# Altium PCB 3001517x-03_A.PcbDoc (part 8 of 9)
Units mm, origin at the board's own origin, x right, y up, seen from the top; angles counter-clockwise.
Board outline 100 x 72 mm, 10 copper layers (Top, GND_2, Signal_3, Signal_4, PWR_5, GND_6, Signal_7, Signal_8, GND_9, Bottom), stack 1.6 mm thick; 602 components, 497 nets, 2372 pads, 1602 vias.
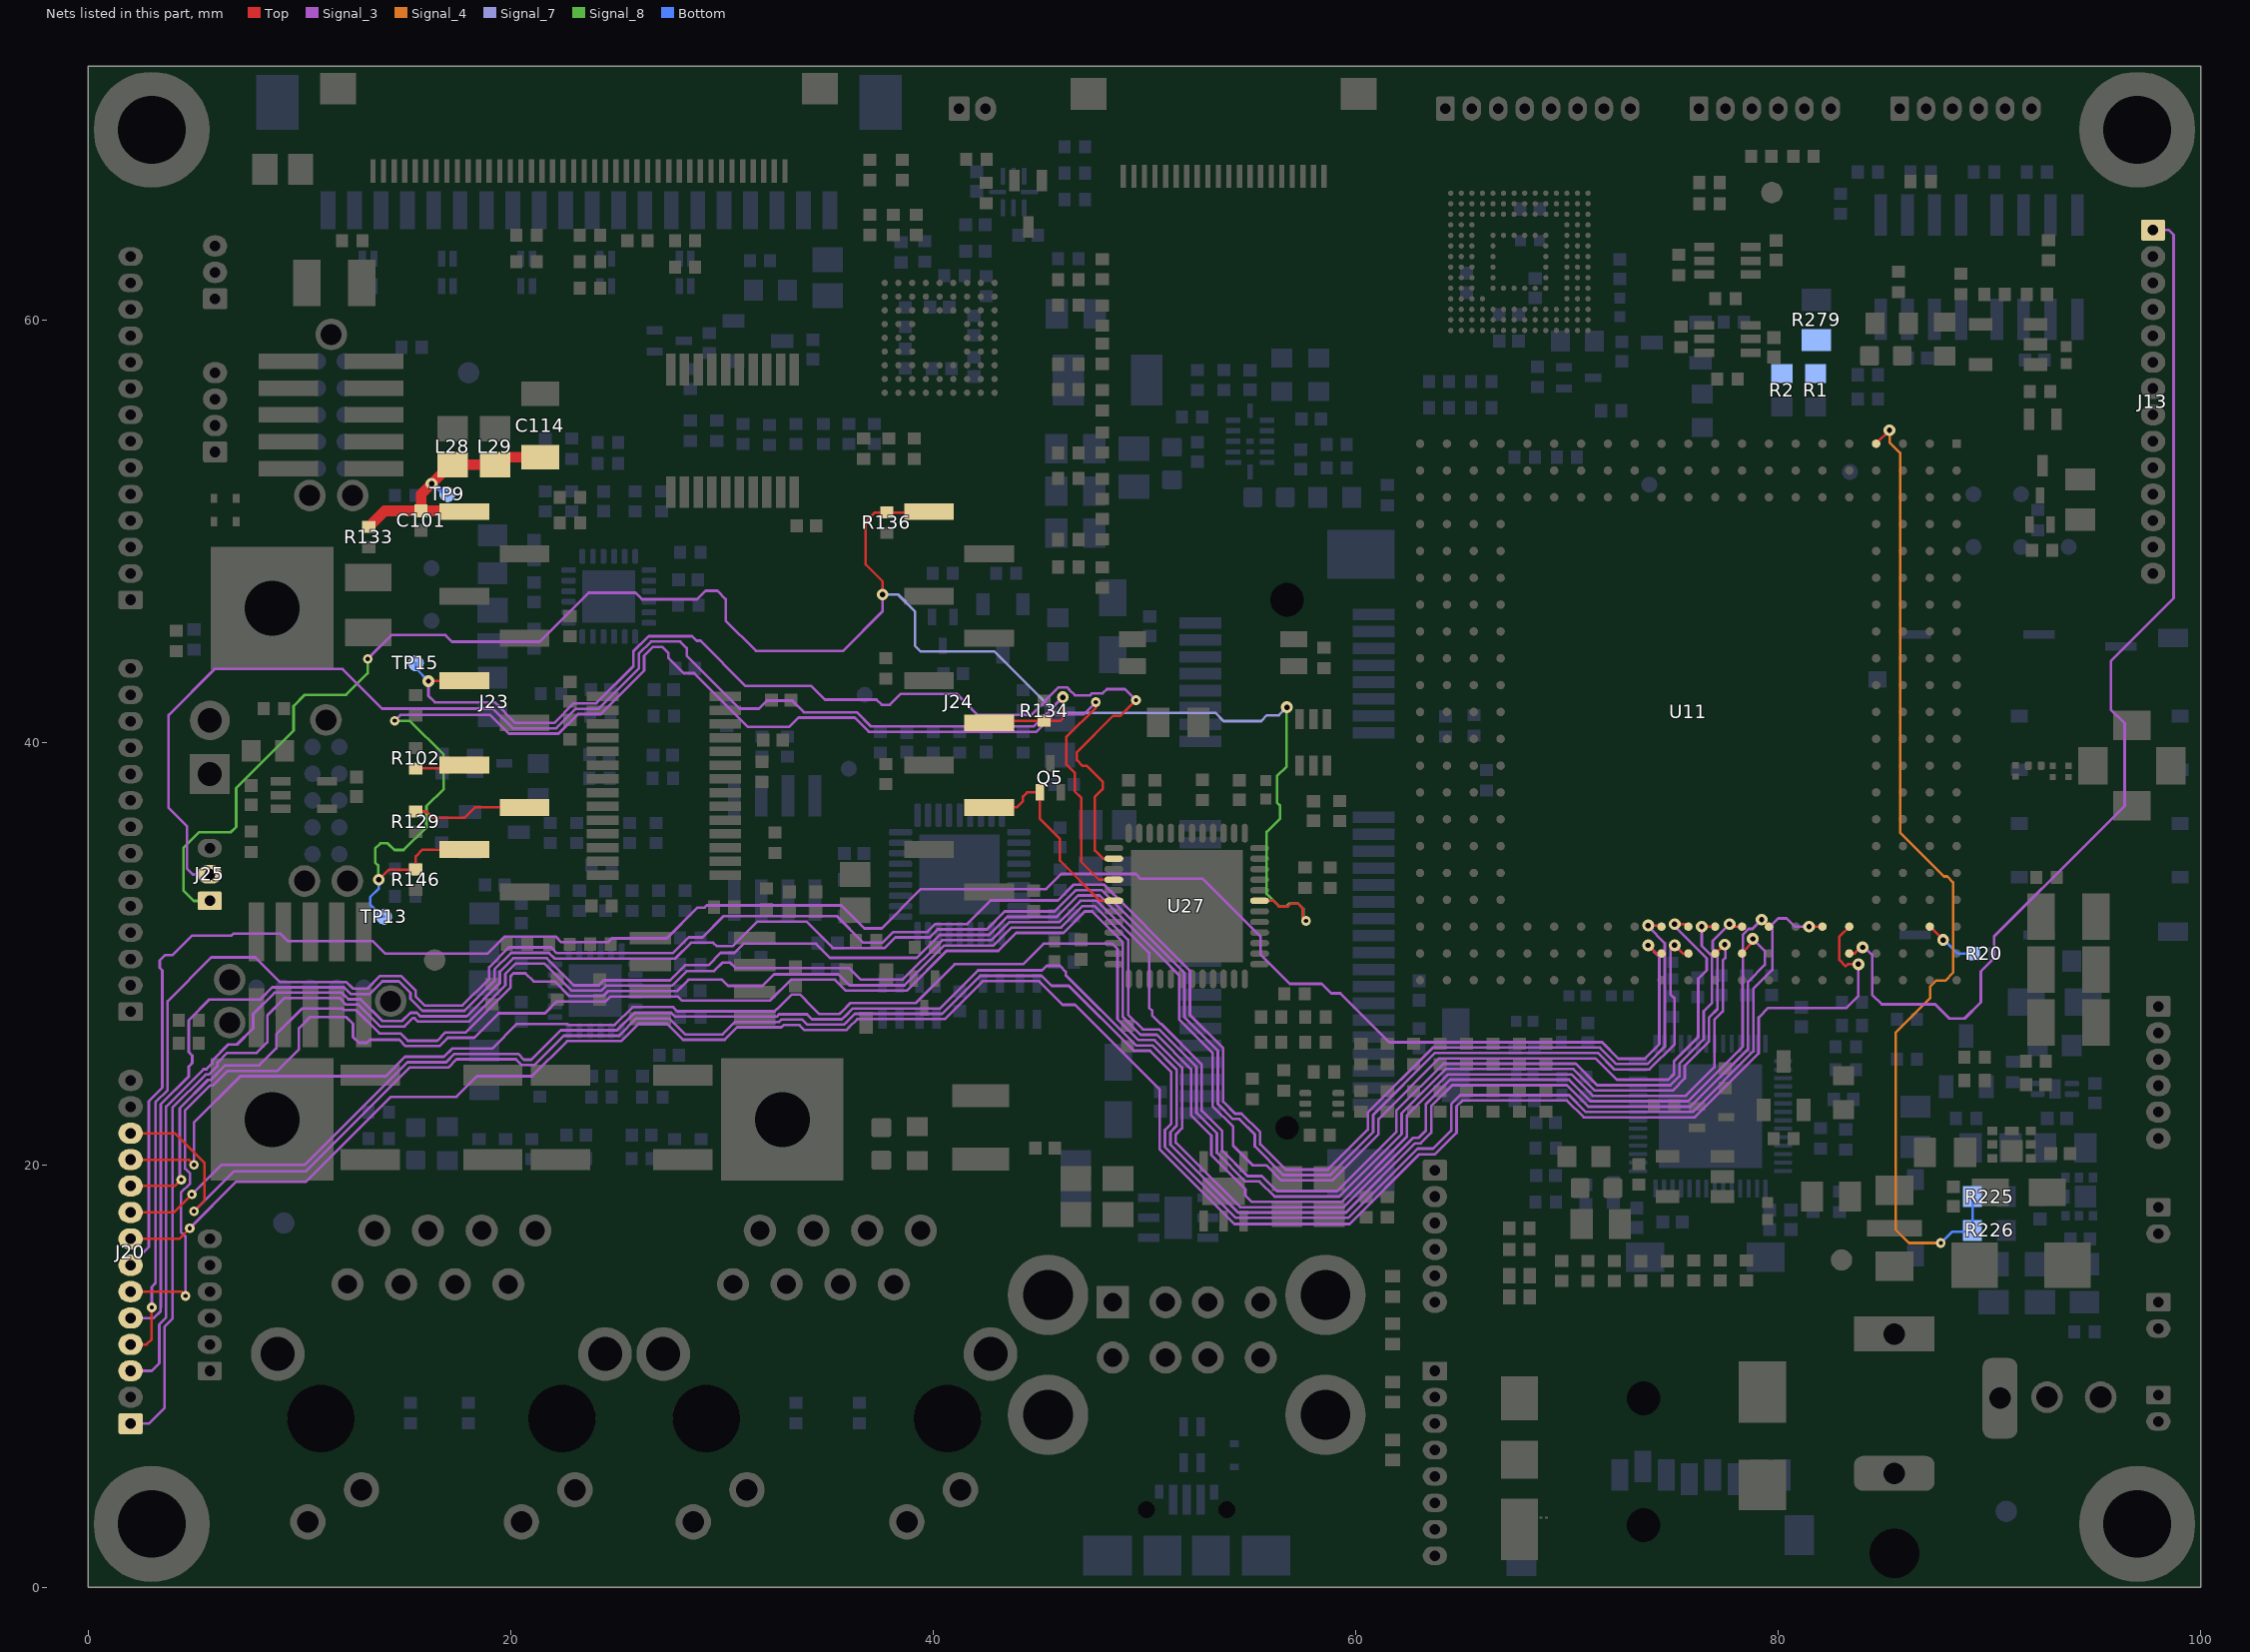
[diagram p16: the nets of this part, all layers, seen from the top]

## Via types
v1: diameter 0.56, hole 0.25, Top to Bottom, tented both sides, 1002 vias
v2: diameter 0.46, hole 0.2, Top to Bottom, tented both sides, 468 vias
v3: diameter 0.457, hole 0.2, Top to Bottom, tented both sides, 132 vias

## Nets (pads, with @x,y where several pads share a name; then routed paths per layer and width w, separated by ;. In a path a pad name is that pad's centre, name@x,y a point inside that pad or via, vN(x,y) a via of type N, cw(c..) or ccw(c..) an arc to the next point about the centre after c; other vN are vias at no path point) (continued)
VPWR: R225.2 R226.2 U11.D1 | length 47.2
  Top w0.125: U11.D1@84.64,54.14 v1(85.275,54.775)
  Signal_4 w0.125: v1(85.275,54.775) 85.275,54.2 85.776,53.699 85.776,35.724 87.845,33.655 88.009,33.655 88.285,33.379 88.285,32.991 88.284,32.109 88.285,31.721 88.284,30.839 88.285,30.451 88.284,29.1 87.909,28.725 87.475,28.725 87.2,28.45 87.2,27.9 85.572,26.272 85.572,16.928 86.2,16.3 v2(87.7,16.3)
  Bottom w0.125: v2(87.7,16.3) 88.23,16.83 89.2,16.83 R226.2@89.2,16.9 R225.2@89.2,18.5
VSYS: R1.1 R2.1 R279.2
WL_EN: J13.1 U11.E20 | length 51.1
  Top w0.119: U11.E20@83.37,30.01 83.624,30.01 84,30.386 v1(84,30.3)
  Signal_3 w0.127: v1(84,30.3) 84,30.395 84.45,29.945 84.45,28.058 84.908,27.6 87.434,27.6 88.105,26.929 88.829,26.929 89.6,27.7 89.6,29.165 90.221,29.786 90.221,30.805 94.788,35.372 96.408,36.992 96.408,40.902 95.753,41.557 95.753,43.853 98.724,46.824 98.724,64.026 98.5,64.25 98.15,64.25 J13.1@97.75,64.25
WLAN_LED: R20.2 U11.B19 | length 2.6
  Top w0.125: U11.B19@87.18,31.28 v1(87.815,30.645)
  Bottom w0.125: v1(87.815,30.645) 87.855,30.645 88.5,30 R20.2@89.27,30
WLAN_SD1_CLK: J20.1 U11.K19 | length 117.2
  Top w0.119: v1(76.385,31.28) U11.K19@77.02,31.28
  Signal_3 w0.127: J20.1@2,7.75 2.858,7.75 3.608,8.5 3.608,12.347 3.981,12.72 3.981,22.699 5.557,24.276 5.691,24.276 6.115,24.7 6.115,24.834 6.582,25.3 7.965,25.3 8.47,25.805 8.47,27.07 9.3,27.9 11.893,27.9 12.208,27.585 12.787,27.585 13.816,26.556 14.962,26.556 15.351,26.946 15.444,26.946 15.605,26.785 18.02,26.785 19.738,28.503 19.738,29.044 20.227,29.532 21.595,29.532 22.881,28.246 24.274,28.246 24.51,28.482 27.642,28.482 28.339,29.179 29.631,29.179 30.029,29.577 30.377,29.577 30.634,29.321 36.014,29.321 36.555,28.78 38.557,28.78 40.416,30.638 42.751,30.638 43.601,31.488 45.95,31.488 46.965,32.503 47.762,32.503 50.22,30.045 50.22,27.445 50.37,27.295 50.37,27.064 50.764,26.67 50.791,26.67 52.714,24.748 52.714,22.57 53.678,21.605 53.678,20.677 54.881,19.475 55.55,19.475 56.265,18.759 59.119,18.759 61.92,21.561 61.92,22.557 64.154,24.791 70.414,24.791 71.43,23.775 74.9,23.775 75.324,24.2 75.324,24.8 76.473,25.948 76.473,27.084 76.473,27.281 76.873,27.681 76.873,29.881 76.385,30.369 v1(76.385,31.28)
WLAN_SD1_CMD: J20.3 U11.L19 | length 114.2
  Top w0.119: v1(75.1,31.4) 75.63,31.4 U11.L19@75.75,31.28
  Signal_3 w0.127: J20.3@2,10.25 3,10.25 3.354,10.604 3.354,12.452 3.683,12.781 3.683,22.761 5.452,24.53 5.586,24.53 5.861,24.805 5.861,24.939 6.622,25.7 7.035,25.7 7.8,26.465 7.8,27.141 8.813,28.154 11.998,28.154 12.313,27.839 12.892,27.839 13.921,26.81 14.856,26.81 15.246,27.2 15.549,27.2 15.71,27.039 17.915,27.039 19.484,28.608 19.484,29.149 20.121,29.786 21.7,29.786 22.986,28.5 24.168,28.5 24.405,28.736 27.536,28.736 28.254,29.454 29.354,29.454 29.939,30.039 30.589,30.039 31.02,30.471 34.446,30.471 35.116,29.8 39.218,29.8 40.31,30.892 42.646,30.892 43.496,31.742 45.845,31.742 46.86,32.757 47.867,32.757 48.883,31.742 50.833,29.792 51.639,28.986 51.639,26.885 53.222,25.302 53.222,22.781 54.2,21.802 54.2,20.9 55.117,19.983 55.761,19.983 56.476,19.267 58.894,19.267 61.079,21.453 61.079,22.174 63.95,25.045 71.35,25.045 72.365,24.029 74.795,24.029 75.07,24.305 75.07,24.905 76.219,26.054 76.219,28.819 76.619,29.219 76.619,29.776 75.1,31.295 v1(75.1,31.4)
WLAN_SD1_D4/GPIO4: J20.8 U11.E19 | length 105.3
  Top w0.119: J20.8@2,16.5 4.3,16.5 v3(4.8,17) ; U11.E19@83.37,31.28 82.9,30.81 82.9,29.7 83.2,29.4 83.3,29.5 v1(83.8,29.5)
  Signal_3 w0.127: v3(4.8,17) 7,19.2 10.3,19.2 14.32,23.22 17.42,23.22 18.4,24.2 21.001,24.2 22.664,25.863 25.236,25.863 26.05,26.677 27.399,26.677 28.151,25.925 30.125,25.925 30.712,26.512 32.808,26.512 32.916,26.62 33.674,26.62 33.911,26.384 35.884,26.384 36.013,26.513 36.016,26.513 36.402,26.9 40.534,26.9 42.332,28.698 45.007,28.698 46.126,27.579 46.713,27.579 50.718,23.575 50.718,20.739 54.257,17.2 59.714,17.2 63.014,20.5 63.754,20.5 64.774,21.521 64.774,22.774 65.05,23.05 70,23.05 70.799,22.251 76.054,22.251 79.079,25.277 79.079,26.974 79.091,26.986 79.091,26.991 79.53,27.43 83.23,27.43 83.8,28 v1(83.8,29.5)
WLAN_SD1_D5/GPIO3: J20.9 U11.J20 | length 100.9
  Top w0.119: J20.9@2,17.75 4.05,17.75 v3(4.9,18.6) ; U11.J20@78.29,30.01 78.29,30.04 78.8,30.55 v1(78.8,30.7)
  Signal_3 w0.127: v3(4.9,18.6) 6.3,20 10.241,20 15.104,24.864 16.939,24.864 17.329,25.254 20.351,25.254 20.626,24.98 20.974,24.98 22.366,26.371 25.025,26.371 25.854,27.2 27.595,27.2 27.775,27.02 32.598,27.02 32.706,27.128 34.025,27.128 34.262,26.892 35.674,26.892 35.803,27.021 35.805,27.021 36.192,27.408 40.323,27.408 42.121,29.206 45.151,29.206 45.366,29.42 45.995,29.42 46.27,29.145 46.27,28.986 49.603,25.654 50.37,25.654 51.524,24.5 51.524,21.849 51.226,21.55 51.226,20.95 54.432,17.743 59.54,17.743 62.822,21.026 63.079,21.026 63.574,21.521 63.574,22.774 64.575,23.775 69.993,23.775 71.009,22.759 75.843,22.759 78.571,25.488 78.571,28.671 79.37,29.47 79.37,30.129 v1(78.8,30.7)
WLAN_SD1_D6/GPIO2: J20.10 U11.J19 | length 107
  Top w0.119: J20.10@2,19 4.1,19 v3(4.4,19.3) ; v1(77.7,31.4) 77.82,31.28 U11.J19@78.29,31.28
  Signal_3 w0.127: v3(4.4,19.3) 4.327,19.373 4.327,22.686 5.662,24.022 5.796,24.022 6.483,24.708 8.09,24.708 8.9,25.518 8.9,26.192 10.108,27.4 12.034,27.4 12.103,27.331 12.669,27.331 13.773,26.227 14.778,26.227 15.126,25.88 16.518,25.88 16.909,26.27 17.865,26.27 19.992,28.398 19.992,28.939 20.124,29.071 20.695,29.071 21.086,28.679 22.088,28.679 22.776,27.992 24.379,27.992 24.615,28.228 27.865,28.228 28.407,28.77 29.995,28.77 30.286,28.479 31.92,28.479 32.465,29.024 35.5,29.024 36.025,28.5 38.637,28.5 40.521,30.384 42.856,30.384 43.706,31.234 46.055,31.234 47.071,32.249 47.629,32.249 49.23,30.649 49.23,27.105 49.919,26.416 50.686,26.416 52.46,24.643 52.46,22.465 53.424,21.5 53.424,20.572 54.776,19.221 55.445,19.221 56.16,18.505 59.224,18.505 62.174,21.456 62.174,22.452 64.259,24.537 70.309,24.537 71.325,23.521 75.005,23.521 75.578,24.095 75.578,24.695 76.727,25.843 76.727,26.979 77.127,27.379 77.127,29.986 76.9,30.213 76.9,30.6 v1(77.7,31.4)
WLAN_SD1_D7/GPIO1: J20.11 U11.H19 | length 104.2
  Top w0.119: J20.11@2,20.25 4.75,20.25 v3(5,20) ; v1(79.221,31.61) 79.23,31.61 U11.H19@79.56,31.28
  Signal_3 w0.127: v3(5,20) 5,22 7.2,24.2 14.082,24.2 14.999,25.118 16.834,25.118 17.224,25.508 19.117,25.508 20.28,26.671 22.676,26.671 22.721,26.625 24.92,26.625 25.761,27.466 27.688,27.466 27.88,27.274 32.493,27.274 32.601,27.382 32.617,27.382 33.126,27.891 33.305,28.071 33.695,28.071 33.97,27.795 33.97,27.77 34.595,27.146 35.568,27.146 35.698,27.275 35.7,27.275 36.087,27.662 39.17,27.662 41.008,29.5 44.256,29.5 45.227,30.471 48.479,30.471 48.722,30.228 48.722,26.895 49.708,25.908 50.476,25.908 51.778,24.605 51.778,21.744 51.48,21.445 51.48,21.055 54.537,17.997 59.434,17.997 62.716,21.28 62.974,21.28 63.32,21.626 63.32,22.88 64.47,24.029 70.099,24.029 71.114,23.013 75.738,23.013 78.317,25.593 78.317,28.777 78.329,28.789 78.329,30.895 78.605,31.17 78.781,31.17 v1(79.221,31.61)
WLAN_SD1_DATA0: J20.4 U11.M19 | length 113.6
  Top w0.119: J20.4@2,11.5 2.75,11.5 3,11.75 v3(3,13.25) ; v1(73.845,31.332) 74.428,31.332 U11.M19@74.48,31.28
  Signal_3 w0.127: v3(3,13.25) 3,14.225 3.175,14.4 3.175,22.971 3.75,23.546 3.75,27.75 5.82,29.82 7.906,29.82 9.064,28.662 12.208,28.662 12.523,28.347 13.219,28.347 13.816,28.944 14.804,28.944 15.504,28.244 15.504,27.964 15.921,27.547 17.705,27.547 18.976,28.819 18.976,29.359 19.911,30.294 21.911,30.294 22.185,30.019 27.666,30.019 28.421,30.774 29.074,30.774 30.074,31.774 35.445,31.774 36.7,30.52 37.595,30.52 38.1,31.024 39.725,31.024 40.1,31.4 41.604,31.4 42.124,31.92 42.125,31.92 42.726,32.52 45.905,32.52 46.65,33.265 48.078,33.265 49.093,32.25 51.043,30.3 ; 51.043,30.3 52.147,29.196 52.147,27.095 53.73,25.513 53.73,22.991 54.291,22.43 54.595,22.43 55.474,21.55 55.474,20.987 56.686,19.775 58.683,19.775 60.571,21.664 60.571,22.471 63.653,25.553 71.56,25.553 72.338,24.775 73.8,24.775 74.63,25.605 74.63,30.496 73.845,31.28 v1(73.845,31.332)
WLAN_SD1_DATA1: J20.5 U11.L20 | length 110.2
  Top w0.119: v1(75.1,30.4) 75.49,30.01 U11.L20@75.75,30.01
  Signal_3 w0.127: J20.5@2,12.75 3.093,12.75 3.419,13.076 3.419,13.24 3.429,13.25 3.429,22.866 4.75,24.187 4.75,24.655 4.92,24.826 4.92,25.174 4.75,25.345 4.75,26.85 5.726,27.826 8.126,27.826 8.708,28.408 12.103,28.408 12.418,28.093 13.324,28.093 13.921,28.69 14.699,28.69 15.25,28.139 15.25,27.859 15.816,27.293 17.81,27.293 19.23,28.713 19.23,29.254 20.016,30.04 21.805,30.04 22.08,29.765 27.771,29.765 28.526,30.52 29.585,30.52 29.755,30.35 30.5,30.35 31.67,31.52 33.995,31.52 35.25,30.266 37.7,30.266 38.205,30.77 39.83,30.77 40.205,31.146 42.541,31.146 43.391,31.996 45.739,31.996 46.755,33.011 47.972,33.011 48.988,31.996 50.938,30.046 51.893,29.091 51.893,26.99 53.476,25.407 53.476,22.886 54.186,22.176 54.49,22.176 55.22,21.445 55.22,20.882 56.581,19.521 58.789,19.521 60.825,21.558 60.825,22.366 63.758,25.299 71.455,25.299 72.232,24.521 73.905,24.521 75.1,25.716 75.1,27.876 74.9,28.076 74.9,30.2 v1(75.1,30.4)
WLAN_SD1_DATA2: J20.6 U11.K20 | length 111.4
  Top w0.119: J20.6@2,14 4.4,14 v3(4.6,13.8) ; U11.K20@77.02,30.01 77.051,30.01 v1(77.47,30.429)
  Signal_3 w0.127: v3(4.6,13.8) 4.6,16.607 4.381,16.826 4.381,18.688 4.819,19.126 4.819,19.588 4.581,19.826 4.581,22.581 5.767,23.768 5.902,23.768 6.588,24.454 8.954,24.454 9.969,25.469 9.969,26.469 10.5,27 12.2,27 12.529,26.671 12.529,26.055 12.805,25.78 13.195,25.78 13.34,25.925 14.721,25.925 15.021,25.626 16.623,25.626 17.014,26.016 18.266,26.016 19.429,27.179 21.619,27.179 22.179,27.738 24.484,27.738 24.721,27.974 27.898,27.974 28.09,27.782 32.282,27.782 33.27,28.77 35.346,28.77 35.87,28.246 38.742,28.246 40.626,30.13 43.08,30.13 43.93,30.98 46.16,30.98 47.176,31.995 47.524,31.995 48.976,30.544 48.976,27 49.813,26.162 50.581,26.162 52.206,24.537 52.206,22.36 53.17,21.395 53.17,20.466 54.78,18.857 54.78,18.555 55.083,18.251 59.329,18.251 62.428,21.351 62.428,22.347 64.365,24.283 70.204,24.283 71.219,23.267 75.633,23.267 76.981,24.616 76.981,26.874 77.381,27.274 77.381,29.681 77.5,29.8 77.5,30.399 v1(77.47,30.429)
WLAN_SD1_DATA3: J20.7 U11.M20 | length 99.8
  Top w0.119: v1(73.845,30.391) 74.226,30.01 U11.M20@74.48,30.01
  Signal_3 w0.127: J20.7@2,15.25 2.86,16.11 2.86,23.015 3.496,23.651 3.496,29.209 3.38,29.326 3.38,29.679 3.625,29.925 3.979,29.925 4.91,30.856 6.773,30.856 6.87,30.953 9.088,30.953 9.441,30.6 13.459,30.6 14.063,29.996 18.896,29.996 19.7,30.8 22.141,30.8 22.246,30.695 22.246,30.674 22.372,30.548 23.171,30.548 23.173,30.546 24.605,30.546 24.785,30.725 27.388,30.725 28.842,32.179 29.174,32.179 29.275,32.28 35.655,32.28 36.738,31.197 37.557,31.197 39.413,33.053 45.344,33.053 46.062,33.771 49.588,33.771 49.817,33.542 52.758,33.542 55.5,30.8 55.5,29.95 56.427,29.023 56.427,29.021 56.878,28.57 58.395,28.57 58.845,28.12 59.274,28.12 61.588,25.807 71.665,25.807 72.443,25.029 73.695,25.029 74.376,25.71 74.376,29.861 v1(73.845,30.391)
WLAN_SDIO_INT_L: J20.12 U11.F19 | length 107
  Top w0.119: J20.12@2,21.5 4.087,21.5 5.5,20.087 5.5,18.3 v3(5,17.8) ; v1(81.465,31.28) U11.F19@82.1,31.28
  Signal_3 w0.127: v3(5,17.8) 6.9,19.7 10.3,19.7 15.209,24.61 17.044,24.61 17.435,25 20.246,25 20.521,24.726 21.118,24.726 22.51,26.117 25.131,26.117 25.944,26.931 27.504,26.931 28.256,26.179 30.02,26.179 30.607,26.766 32.703,26.766 32.811,26.874 33.8,26.874 34.036,26.638 35.779,26.638 35.908,26.767 35.91,26.767 36.297,27.154 40.429,27.154 42.227,28.952 45.133,28.952 45.605,28.48 46.418,28.48 49.498,25.4 50.265,25.4 51.27,24.395 51.27,21.954 50.972,21.655 50.972,20.845 54.327,17.489 59.645,17.489 62.927,20.772 63.666,20.772 64.52,21.626 64.52,22.88 64.945,23.304 70.105,23.304 70.904,22.505 75.948,22.505 78.825,25.382 78.825,28.325 79.725,29.224 79.725,31.39 80.005,31.67 80.395,31.67 80.785,31.28 v1(81.465,31.28)
XBEE_ASSOC: J24.6 J25.2 R134.1 | length 62.7
  Top w0.119: J24.6@42.65,40.925 42.745,41.02 R134.1@45.25,41.02 46.02,41.02 46.135,41.135 v1(46.135,42.135)
  Signal_3 w0.127: J25.2@5.75,33.75 4.95,33.75 4.666,34.034 4.666,36.034 3.8,36.9 3.8,41.3 5.971,43.47 12.035,43.47 13.905,41.6 19.158,41.6 20.09,40.668 22.154,40.668 23.079,41.593 24.153,41.593 26.059,43.499 26.059,44.2 26.633,44.774 28.02,44.774 28.329,44.465 28.329,44.105 30.834,41.6 31.75,41.6 32.122,41.972 33.322,41.972 33.868,41.426 36.384,41.426 37.056,40.754 44.754,40.754 v1(46.135,42.135)
XBEE_IDENT/IO33: J24.1 J25.1 R136.1 U27.43 | length 92.5
  Top w0.119: v1(37.6,47) 37.6,47.616 36.8,48.416 36.8,50.45 37.23,50.88 R136.1@37.8,50.88 39.755,50.88 J24.1@39.8,50.925 ; U27.43@55.45,32.5 56.113,32.5 56.378,32.235 56.796,32.235 56.927,32.366 57.273,32.366 57.516,32.123 57.516,31.684 v3(57.65,31.55)
  Signal_3 w0.127: v3(13.226,43.95) 14.354,45.078 16.905,45.078 17.216,44.767 21.368,44.767 23.678,47.078 25.905,47.078 26.211,46.773 28.819,46.773 29.221,47.175 29.779,47.175 30.174,46.779 30.174,45.761 31.601,44.334 35.734,44.334 37.6,46.2 v1(37.6,47)
  Signal_8 w0.127: J25.1@5.75,32.5 5,32.5 4.5,33 4.5,35 5.25,35.75 6.75,35.75 7,36 7,37.835 9.72,40.555 9.72,41.72 10.25,42.25 12.201,42.25 13.226,43.274 v3(13.226,43.95) ; v1(56.743,41.661) 56.728,41.647 56.728,38.862 56.272,38.405 56.272,37.153 56.424,37 56.424,36.4 55.782,35.757 55.782,32.826 56.376,32.231 56.724,32.231 56.863,32.37 57.274,32.37 57.52,32.124 57.52,31.679 v3(57.65,31.55)
  Signal_7 w0.127: v1(37.6,47) 38.335,47 39.133,46.201 39.133,44.567 39.401,44.299 42.901,44.299 45.8,41.4 53.353,41.4 53.746,41.007 55.523,41.007 55.799,41.283 56.365,41.283 v1(56.743,41.661)
XBEE_ON/SLP_N/IO11: J24.8 Q5.G U27.18 | length 9.8
  Top w0.119: J24.8@42.65,36.925 43.956,36.925 44.25,37.219 44.25,37.446 44.439,37.635 Q5.G@45.05,37.635 45.05,36.375 46,35.425 46,34.4 47.9,32.5 U27.18@48.55,32.5
XBEE_RSTN/IO7: J23.5 TP15.1 U27.14 | length 53
  Top w0.119: v1(16.1,42.9) 17.775,42.9 J23.5@17.8,42.925 ; U27.14@48.55,34.5 48.04,34.5 47.658,34.882 47.658,37.429 48.015,37.786 48.015,38.144 47.28,38.88 47.075,38.88 46.802,39.153 46.802,39.539 48.524,41.261 48.861,41.261 v2(49.6,42)
  Signal_3 w0.127: v1(16.1,42.9) 16.1,42.2 16.4,41.9 19.242,41.9 20.22,40.922 22.049,40.922 22.974,41.847 24.048,41.847 25.805,43.604 25.805,44.306 26.528,45.028 28.584,45.028 28.801,44.812 28.974,44.812 31.115,42.671 34.223,42.671 34.874,42.02 37.314,42.02 37.555,41.779 37.945,41.779 38.465,42.3 41.1,42.3 42.1,41.3 44.635,41.3 45.941,42.606 46.331,42.606 46.429,42.508 46.429,42.505 46.705,42.229 47.435,42.229 47.526,42.32 48.02,42.32 48.22,42.52 49.08,42.52 v2(49.6,42)
  Bottom w0.119: TP15.1@15.5,43.75 15.5,43.5 v1(16.1,42.9)
XBEE_SLP_RQ/IO9: J23.9 R146.2 TP13.1 U27.16 | length 67.5
  Top w0.119: v1(13.75,33.5) 14.23,33.98 R146.2@15.5,33.98 15.5,34.6 15.825,34.925 J23.9@17.8,34.925 ; v2(47.7,41.9) 47.7,41.655 46.31,40.265 46.31,38.949 46.695,38.565 46.695,37.685 46.999,37.381 46.999,34.351 47.85,33.5 U27.16@48.55,33.5
  Signal_3 w0.127: v3(14.5,41.025) 14.775,41.3 19.022,41.3 19.908,40.414 22.259,40.414 23.184,41.339 24.258,41.339 26.313,43.394 26.313,44.095 26.738,44.52 27.174,44.52 27.464,44.231 27.464,44 27.489,43.974 27.489,43.969 28.185,43.272 28.685,43.272 31.228,40.729 33.178,40.729 33.621,41.172 36.278,41.172 36.951,40.5 44.889,40.5 45.731,41.342 47.142,41.342 v2(47.7,41.9)
  Signal_8 w0.127: v1(13.75,33.5) 13.72,33.529 13.72,34.174 13.579,34.315 13.579,34.974 13.826,35.22 14.174,35.22 14.49,34.905 14.927,34.905 16.003,35.981 16.003,36.981 16.822,37.801 16.822,39.412 15.209,41.025 v3(14.5,41.025)
  Bottom w0.119: v1(13.75,33.5) 13.75,33.087 13.335,32.672 13.335,32.328 13.444,32.219 13.913,31.75 TP13.1@14,31.75
XBEE_USB_N: J23.8 R129.2 | length 5.5
  Top w0.127: R129.2@15.5,36.73 16.008,36.73 16.309,36.429 17.804,36.429 18.301,36.925 J23.8@20.65,36.925
XBEE_USB_P: J23.7 R102.2 | length 2.4
  Top w0.127: R102.2@15.5,38.77 17.645,38.77 J23.7@17.8,38.925
XBEE_VCC: C101.2 C114.2 J23.1 L28.2 L29.2 R133.1 TP9.1 | length 13.1
  Top w0.5: R133.1@13.275,50.205 14.03,50.96 C101.2@15.75,50.96 ; J23.1@17.8,50.925 17.765,50.96 C101.2@15.75,50.96 ; C114.2@21.395,53.5 19.25,53.5 L29.2@19.25,53.15 L28.2@17.25,53.15 17.15,53.15 v1(16.25,52.25) 15.75,51.75 C101.2@15.75,50.96
  Bottom w0.25: v1(16.25,52.25) TP9.1@17,51.75
pads on no net: CAD1.7 CAD1.MT1 CAD1.MT2 CAD1.MT3 CAD2.6 CAD2.7 CAD2.8 CAD2.9 CAD2.MT1 CAD2.MT2 CAD2.MT3 CAD3.6 CAD3.7 CAD3.8 CAD3.9 CAD3.MT1 CAD3.MT2 CAD3.MT3 FIDUCIAL1.1 FIDUCIAL2.1 FIDUCIAL3.1 FIDUCIAL4.1 FIDUCIAL5.1 FIDUCIAL6.1 FIDUCIAL7.1 FIDUCIAL8.1 FIDUCIAL9.1 FIDUCIAL10.1 FIDUCIAL11.1 FIDUCIAL12.1 H1.1 H2.1 H3.1 H4.1 J1.3 J1.4 J6.7 J6.MNT1 J6.MNT2 J8.7 J8.MNT1 J8.MNT2 J11.6 J11.7 J11.8 J12.3 J12.5 J12.6 J12.7 J12.11 J12.13 J12.17 J12.19 J12.22 J12.23 J12.25 J12.28 J12.31 J12.33 J12.42 J12.44 J12.45 J12.46 J12.47 J12.48 J12.49 J12.51 J12.H1 J12.H2 J12.MT1 J12.MT2 J14.4 J14.8 J14.9 J14.10 J16.10 J16.11 J17.M1 J17.M2 J21.M1 J21.M2 J22.4 J22.5 J22.MT1 J22.MT2 J24.2 J24.3 J24.4 J29.3 J29.4 J30.10 J31.MT1 J31.MT21 J37.6 J37.7 J37.8 U2.A1 U2.A2 U2.A6 U2.A7 U2.A8 U2.A9 U2.A10 U2.A11 U2.A12 U2.A13 U2.A14 U2.B1 U2.B7 U2.B8 U2.B9 U2.B10 U2.B11 U2.B12 U2.B13 U2.B14 U2.C1 U2.C3 U2.C5 U2.C7 U2.C8 U2.C9 U2.C10 U2.C11 U2.C12 U2.C13 U2.C14 U2.D1 U2.D2 U2.D3 U2.D4 U2.D12 U2.D13 U2.D14 U2.E1 U2.E2 U2.E3 U2.E5 U2.E8 U2.E9 U2.E10 U2.E12 U2.E13 U2.E14 U2.F1 U2.F2 U2.F3 U2.F10 U2.F12 U2.F13 U2.F14 U2.G1 U2.G2 U2.G3 U2.G10 U2.G12 U2.G13 U2.G14 U2.H1 U2.H2 U2.H3 U2.H5 U2.H12 U2.H13 U2.H14 U2.J1 U2.J2 U2.J3 U2.J5 U2.J12 U2.J13 U2.J14 U2.K1 U2.K2 U2.K3 U2.K5 U2.K6 U2.K7 U2.K10 U2.K12 U2.K13 U2.K14 U2.L1 U2.L2 U2.L3 U2.L12 U2.L13 U2.L14 U2.M1 U2.M2 U2.M3 U2.M7 U2.M8 U2.M9 U2.M10 U2.M11 U2.M12 U2.M13 U2.M14 U2.N1 U2.N3 U2.N6 U2.N7 U2.N8 U2.N9 U2.N10 U2.N11 U2.N12 U2.N13 U2.N14 U2.P1 U2.P2 U2.P7 U2.P8 U2.P9 U2.P10 U2.P11 U2.P12 U2.P13 U2.P14 U6.11 U6.12 U6.13 U6.14 U6.28 U6.29 U6.40 U6.41 U6.46 U9.7 U9.8 U9.15 U9.16 U9.20 U9.21 U11.A1 U11.B3 U11.B4 U11.B7 U11.B8 U11.B9 U11.B10 U11.B11 U11.C6 U11.C7 U11.C8 U11.C9 U11.C10 U11.C15 U11.C16 U11.D6 U11.D11 U11.M3 U11.N2 U11.R2 U11.T2 U11.T3 U11.T20 U11.U2 U11.U3 U11.W4 U11.W9 U11.Y3 U11.Y5 U11.Y6 U11.Y18 U12.3 U12.5 U13.18 U13.19 U16.4 U20.2 U20.6 U21.6 U24.4 U25.A6 U25.A7 U25.A8 U25.A9 U25.B6 U25.B7 U25.B8 U25.B9 U25.C8 U25.C9 U31.1

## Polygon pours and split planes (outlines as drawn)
GND on Top "NONET_L01_P137" (solid, remove dead copper, shelved, pour order 137): 0,0 0,72 100,72 100,0
NetFIL1_1 on Top "NONET_L01_P135" (solid, remove dead copper, shelved, pour order 135): 25 vertices, not listed, extent 83.6,4.2 93.7,12.9
NetR2_2 on Bottom "NONET_L10_P131" (solid, remove dead copper, shelved, pour order 131): 80.75,56.5 80.75,52 80.5,51.75 78.5,51.75 78.5,52.75 79.25,53.5 79.5,53.75 79.5,56.5
NetR1_2 on Bottom "NONET_L10_P133" (solid, remove dead copper, shelved, pour order 133): 81.25,56.5 81.25,55.5 81,55.25 81,52.75 81,52 81.25,51.75 83,51.75 83,53 82.5,53.5 82.5,56.5
GND on Bottom "NONET_L10_P139" (solid, remove dead copper, shelved, pour order 139): 0,0 100,0 100,72 0,72
GND on Signal_3 "NONET_L03_P141" (solid, remove dead copper, shelved, pour order 141): 0,0 100,0 100,72 0,72
GND on Signal_4 "NONET_L04_P143" (solid, remove dead copper, shelved, pour order 143): 0,0 100,0 100,72 0,72
GND on Signal_7 "NONET_L07_P145" (solid, remove dead copper, shelved, pour order 145): 0,0 100,0 100,72 0,72
GND on Signal_8 "NONET_L08_P147" (solid, remove dead copper, shelved, pour order 147): 0,0 100,0 100,72 0,72
GND on GND_2 (split plane): 99.49,0.51 0.51,0.51 0.51,71.49 99.49,71.49
NetR2_2 on PWR_5 (split plane): 80.673,51.542 78.327,51.542 78.327,52.347 78.653,52.673 79.1,52.673 79.149,52.682 79.19,52.71 79.65,53.17 79.678,53.211 79.687,53.26 79.687,55.007 79.973,55.293 80.673,55.293
3V3 on PWR_5 (split plane): 80.25,69.027 64,69.027 64,70.998 80.25,70.998
NetR39_2 on PWR_5 (split plane): 36 vertices, not listed, extent 71.527,51.542 79.612,55.293
3V3_EMMC on PWR_5 (split plane): 72.173,62.547 72.173,60.273 71.727,59.827 65.953,59.827 65.527,60.253 65.527,63.547 66.953,64.973 69.747,64.973
LDO4_1V8 on PWR_5 (split plane): 40.273,59.5 40.282,59.451 40.31,59.41 40.351,59.382 40.4,59.373 41.573,59.373 41.573,59.25 41.573,58.24 41.377,58.044 39.427,58.044 39.427,60.447 39.653,60.673 40.273,60.673
NetL1_1 on PWR_5 (split plane): 18 vertices, not listed, extent 50.852,52.752 53.848,58.048
NetC56_2 on PWR_5 (split plane): 34 vertices, not listed, extent 81.227,16.327 95.973,62.773
3V3 on PWR_5 (split plane): 207 vertices, not listed, extent 36.055,24.927 91.463,69.173
VIN_PROT on PWR_5 (split plane): 94 vertices, not listed, extent 46.527,10.027 89.573,55.973
NetR1_2 on PWR_5 (split plane): 31 vertices, not listed, extent 80.927,51.541 87.053,55.293
1V8_CODEC on PWR_5 (split plane): 18 vertices, not listed, extent 74.327,15.527 80.573,28.02
3V3_CODEC on PWR_5 (split plane): 29 vertices, not listed, extent 76.737,16.727 85.445,26.393
PCIE_VCC on PWR_5 (split plane): 177 vertices, not listed, extent 17.927,21.227 66.173,60.473
5V_DISPLAY on PWR_5 (split plane): 27 vertices, not listed, extent 6.977,59.327 35.8,68.273
NetC72_2 on PWR_5 (split plane): 43 vertices, not listed, extent 35.917,28.227 46.533,40.073
3V3_ETH on PWR_5 (split plane): 41 vertices, not listed, extent 16.927,44.78 29.873,55.073
VIN_PROT on PWR_5 (split plane): 22 vertices, not listed, extent 13.727,31.09 16.598,51.618
3V3_ETH on PWR_5 (split plane): 52 vertices, not listed, extent 17.127,26.348 30.373,37.373
VCC_MCA on PWR_5 (split plane): 143 vertices, not listed, extent 5.127,18.429 95.973,70.65
3V3 on PWR_5 (split plane): 594 vertices, not listed, extent 1.002,1.002 98.998,68.4
5V on PWR_5 (split plane): 243 vertices, not listed, extent 30.027,14.577 98.998,66.773
NetD10_2 on PWR_5 (split plane): 67 vertices, not listed, extent 34.002,4.927 56.073,36.145
AVDD2 on PWR_5 (split plane): 132 vertices, not listed, extent 15.227,1.952 28.473,45.273
AVDD1 on PWR_5 (split plane): 61 vertices, not listed, extent 19.927,2.002 42.273,28.073
SHLD on GND_6 (split plane): 191 vertices, not listed, extent 7.176,0.51 82.949,17.999
GND on GND_6 (split plane): 212 vertices, not listed, extent 0.51,0.51 99.49,71.49
GND on GND_9 (split plane): 99.49,0.51 0.51,0.51 0.51,71.49 99.49,71.49

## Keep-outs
Keep-Out Layer:
  lines w0.1: 68.471,50.54 83.093,50.54 cw(c83.093,50.053) 83.58,50.053 83.58,32.863 cw(c83.057,32.863) 83.057,32.34 68.5,32.34 cw(c68.5,32.92) 67.92,32.92 67.92,49.96 cw(c68.5,49.96) 68.5,50.54
  lines w0.25: 0,0 0,72 100,72 100,0 0,0

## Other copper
Top:
  rectangle net 5V_DISPLAY: 6.9,66.4 8.253,67.8
  rectangle net GND: 69.759,17.325 70.575,18.9
  pour cut-out: 64,59 64,66.5 71.5,66.5 71.5,59
  region net VIN: 86.1,24.3 88.2,24.3 88.2,23.3 89.3,23.3 90.633,21.967 91.4,21.967 91.4,21.4 89.9,21.4 89.4,21.9 88,21.9 87.5,21.4 87.5,19.9 86.4,18.8 86.4,18.1 84.6,18.1 84.6,20.4 86.1,21.9
  region net VIN_PROT: 88.2,14.1 88.2,16.5 89.1,17.4 89.1,18.308 88.808,18.6 87.9,18.6 87.7,18.4 87.4,18.4 87.3,18.6 87.3,19.4 88.3,20.4 88.3,21.4 89.4,21.4 89.625,21.175 92.925,21.175 93.2,20.9 93.2,20.034 91.531,20.034 91,19.503 91,14.6 90.5,14.1
  region net NetFIL1_1: 83.6,12.3 83.6,13.5 84.6,14.5 84.6,15.1 86.4,15.1 86.4,14.5 87.4,13.5 87.4,12.3
  text ".Layer_Name" at 41.25,-18.875 h2.54
Signal_3:
  text ".Layer_Name" at 41.25,-18.875 h2.54
Signal_8:
  text ".Layer_Name" at 41.047,-19 h2.54
Signal_4:
  text ".Layer_Name" at 41.25,-18.875 h2.54
Signal_7:
  text ".Layer_Name" at 41.25,-18.875 h2.54
Bottom:
  rectangle net SHLD: 80.3,0.9 81.7,1.8
  rectangle net SHLD: 66,0.6 67.7,1.9
  rectangle net SHLD: 46,0.525 58,2.5
  rectangle net PCIE_VCC: 47.2,21.4 48.7,22.8
  rectangle net NetL1_1: 50.3,56.4 51.6,57.8
  rectangle net NetC56_2: 81.1,61.4 82.5,62.7
  pour cut-out: 73.75,19.25 80,19.25 80,25.5 73.75,25.5
  region net PCIE_VCC: 48.9,48.1 50,48.1 50.5,47.6 50.5,46 49.5,46 48.9,46.6
  region net PCIE_VCC: 45.3,61 45.3,58.6 45.6,58.3 45.6,54.9 45.2,54.5 45.2,49.2 46.4,49.2 46.6,49.4 46.6,54.3 46.1,54.8 46.1,55.3 46.8,56 47.1,56 47.1,58.08 46.88,58.3 46.5,58.3 46.5,60.9 46.4,61
  region net 5V: 32,61.9 30.5,61.9 30,61.4 30,59.8 30.2,59.6 31.1,59.6 31.1,60.2 31.7,60.8 32,60.8
  region net 5V_DISPLAY: 32.3,58.649 32.3,59.5 32.7,59.9 32.7,61.9 35.6,61.9 35.7,61.8 35.7,60.3 34.6,59.2 34.6,58.8 33.551,58.8 33.4,58.649
  region net VSYS: 81.1,58.7 82.5,58.7 82.5,57.2 82.3,57 79.6,57 79.6,57.8 79.7,57.9 80.8,57.9 81.1,58.2
  region net VIN_PROT: 88,18.4 88,19.3 89.6,19.3 89.6,21.5 88.2,21.5 87.7,21 87.7,19.9 87.3,19.5 87.3,18.4
  region net NetC55_2: 93.8,18.1 93.8,19.625 93.2,20.225 93.2,21.5 90.5,21.5 90.3,21.3 90.3,18.1 92,18.1
  region net NetC56_2: 94,21.5 95.1,21.5 95.1,18.2 95.3,18 95.6,18 95.8,17.8 95.8,16.8 95.8,16.5 95.6,16.3 95.3,16 95.3,14.8 89.5,14.8 89.5,15.9 94.308,15.9 94.5,16.092 94.5,17 94.3,17.2 94,17.2
  region net VIN: 88.3,24.3 87.3,24.3 87.092,24.092 86.392,24.092 85.8,23.5 85.8,22.225 85.825,22.2 87.2,22.2 87.2,22.6 87.7,23.1 88.3,23.1
  region net VIN_PROT: 49.6,55.8 49.6,54.4 50.2,53.8 52,53.8 52.1,53.9 52.8,53.9 52.8,54.5 52.5,54.8 51.2,54.8 51.1,54.9 51.1,55.8
  region net PCIE_VCC: 65.4,28.1 66,27.5 66,27.1 65.3,26.4 62.7,26.4 62.7,27.79 64.09,27.79 64.4,28.1
  region net NetL1_1: 53.975,53.875 53.65,53.875 53.5,54.025 53.225,54.025 53.025,53.825 53.025,52.975 53.125,52.875 53.525,52.875 53.685,53.035 53.685,53.46 53.85,53.625 54,53.625
  pour cut-out: 73.8,32 73.8,28.346 75.9,28.346 75.9,29.919 75.4,29.919 75.4,32
  pour cut-out: 77,28.5 77,30 81,30 81,28.5
  pour cut-out: 70.9,20.3 70.9,18.4 72.2,18.4 72.2,20.3
  region net 5V: 91,28.9 92.552,28.9 92.752,29.1 92.752,30.2 91.8,30.2 91,29.4
  region net NetC8_2: 93.4,30.157 94.343,30.157 95.35,29.15 95.35,23.55 95.3,23.5 94.592,23.5 94.492,23.6 94.492,24.53 93.4,25.622
  text "30015172-02 BOT" at 3.5,48 h1 r270
  text ".Layer_Name" at 37.526,-19 h2.54
GND_2 (plane layer: these items are gaps in the copper):
  text "NEGATIVE IMAGE" at 41,-15 h2.54
  text ".Layer_Name" at 41.25,-18.875 h2.54
PWR_5 (plane layer: these items are gaps in the copper):
  pour cut-out: 25,40.75 25,42.5 26.75,42.5 26.75,40.75
  region: 0,71.5 0.5,72 2.75,72 2.75,53 2.25,52.5 -0.05,52.5
  region: 0,0 2.75,0 2.75,50.5 2.5,50.75 -0.5,50.75
  region: 96.9,18.7 96.85,18.75 96.1,18 95.4,18 94.6,18.8 94.6,47.9 96.1,49.4 96.1,63.1 90.3,68.9 80.25,68.9 80.25,72.05 99.95,72.05 100,72 100,19.45 99.25,18.7
  region: 0,67 3.25,67 4.65,68.4 5.5,68.4 7,69.9 40.35,69.9 41.05,69.2 42.8,69.2 44.25,70.65 61.85,70.65 63.6,68.9 64,68.9 64,72.05 0.3,72.05 0,71.75
  region: 100.049,12 97.25,12 97.25,6 94,2.75 43.5,2.75 40.75,0 100,0
  region: 0,0 2.75,2.75 16,2.75 18.75,0
  region: 22.513,-0.25 25.513,2.75 35,2.75 38,-0.25
  lines w0.25: 8.55,57.842 6.642,59.75 5.45,59.75 5,60.2 5,61 5,65.25 5.5,65.75 5.5,68.4 7,69.9 40.35,69.9 41.05,69.2 42.8,69.2 44.25,70.65 ; 12.25,58.7 11.2,58.7 8.75,61.15 8.75,64.25 7.4,65.6 ; 13.6,42.3 13.6,50.6 ; 13.6,42.5 13.6,38.9 14.1,38.4 14.1,31.919 15.1,30.919 ; 14.8,51.8 15.4,51.2 15.4,42 ; 15.375,42.1 15.375,34.097 16.172,33.3 16.725,33.3 ; 19.8,27 19.8,25.3 21.5,23.6 21.5,18.8 29.4,18.8 29.4,21.6 31.8,24 33.7,24 35.5,22.2 37.7,22.2 40.2,19.7 40.2,13.9 36.9,10.6 36.9,3.05 38.075,1.875 39.45,1.875 40.1,2.525 40.1,5.9 38.9,7.1 38.9,8.8 42.4,12.3 42.4,20.7 38,25.1 31.215,25.1 29.967,26.348 ; 21.5,21.4 21.5,18.9 22.6,17.8 22.6,11.1 20.6,9.1 20.6,5.5 21.9,4.2 21.9,2.5 21.225,1.825 19.775,1.825 19,2.6 19,3 19,15.4 19.7,16.1 19.7,17.1 16.4,20.4 16.4,23.7 15.7,24.4 15.7,26.7 15.1,27.3 15.1,30.9 16.725,32.525 16.725,36.025 19.9,39.2 21.3,39.2 21.9,39.8 21.9,41.1 21.3,41.7 19.1,41.7 17.2,43.6 17.2,44.6 ; 32.9,62 32.9,60.1 ; 32.9,62.3 30.5,62.3 29.9,61.7 29.9,58.575 31.275,57.2 34.85,57.2 35.15,56.9 38.283,56.9 39.3,57.917 ; 33.5,67.453 37.822,67.453 37.974,67.3 40.9,67.3 41.3,67.7 41.8,68.2 45.4,68.2 46.5,69.3 53.9,69.3 54.5,68.7 55.907,68.7 56.407,68.2 83.8,68.2 88.18,63.82 88.18,62.9 ; 35.927,65.3 35.927,64.95 40.7,64.95 42.15,66.4 47,66.4 47.5,66.9 62.1,66.9 65.4,63.6 ; 41.4,28.1 42.275,28.1 ; 41.8,28.1 42.275,28.1 ; 61.85,70.65 63.6,68.9 90.3,68.9 96.1,63.1 96.1,49.4 94.6,47.9 ; 68.3,50.7 65.9,53.1 65.9,54.75 66.4,55.25 66.4,58.6 65.9,59.1 65.9,59.7 ; 75.6,50.54 75.6,52.5 75.5,52.6 71.9,52.6 71.4,53.1 71.4,53.8 72,54.4 75.5,54.4 75.8,54.7 75.8,55 76.22,55.42 79.92,55.42 ; 76.61,16.6 77.4,16.6 77.907,17.107 79.707,17.107 81.152,18.552 81.152,19.852 83.8,22.5 85.572,22.5 85.572,23.8 85.172,24.2 83.8,24.2 81.479,26.521 80.7,26.521 ; 78.2,50.9 78.2,52.4 78.6,52.8 79.1,52.8 79.56,53.26 79.56,55.06 79.92,55.42 ; 80.7,27.2 80.7,27.408 ; 80.8,51.3 80.8,55.42 ; 83.142,32.158 86,29.3 86,27.3 88.5,24.8 91.59,24.8 ; 83.3,51.3 83.3,52.2 84,52.9 86.7,52.9 87.18,53.38 87.18,54.72 86.48,55.42 85.32,55.42 85,55.1 84.4,55.1 84.08,55.42 80.8,55.42 ; 84.5,22.5 87.1,22.5 89.7,19.9 89.7,17.9 87.5,17.9 79.5,9.9 65.2,9.9 61.6,13.5 51.5,23.6 51.5,25.5 50.8,26.2 ; 84.7,22.5 84.7,20.132 77.968,13.4 71.6,13.4 70.8,14.2 70.8,17.4 65.5,22.7 62.3,22.7 58.9,22.7 ; 89.7,18.992 89.7,16.727 91.977,14.45 99.75,14.45 100,14.7 ; 99.1,16.8 99.1,19 ; 100.05,18.7 96.8,18.7 96.1,18 ; 7.4,65.6 6.85,66.15 6.85,67.675 7.575,68.4 13,68.4 13.947,67.453 14.4,67 23.05,67 23.503,67.453 35.927,67.453 35.927,60.027 35.1,59.2 33.8,59.2 32.9,60.1 ; 7.4,65.6 31.4,65.6 32.9,64.1 32.9,60.1 ; 17.2,44.6 18,45.4 25.832,45.4 26.453,44.778 27.922,44.778 ; 17.2,44.6 16.8,45 16.8,46.6 19.9,49.7 21.6,49.7 22.1,50.2 22.1,53.9 23.4,55.2 24.775,55.2 25.1,54.875 25.926,54.875 26.4,54.4 26.4,49.4 27.1,48.7 29.3,48.7 30,48 30,45.8 29.2,45 28.143,45 27.922,44.778 ; 26.365,37.135 27.845,37.135 28.1,37.39 28.1,38.4 27.8,38.7 27.8,40.207 28.6,41.007 28.6,42.743 28.3,43.043 28.3,44.4 27.922,44.778 ; 26.365,37.135 26,37.5 25.1,37.5 23.3,35.7 20.8,35.7 18.9,33.8 18.9,30.667 17,28.767 17,28.2 17.8,27.4 18.1,27.4 18.5,27 21.6,27 22.8,28.2 26.6,28.2 28.58,26.22 30.02,26.22 30.5,26.7 30.5,27.1 30,27.6 29.4,27.6 26.7,30.3 26.7,32.2 26.7,34.2 26.365,34.535 26.365,37.135 ; 35.79,36.273 34.273,36.273 33.875,35.875 33.875,30.725 37.4,27.2 39.5,27.2 41.7,25 42.2,25 43.6,23.6 43.6,20.3 48.7,15.2 51,15.2 51.9,14.3 51.9,6.1 53.2,4.8 55.1,4.8 56.2,5.9 56.2,8.6 54.468,10.332 54.468,14.932 49.636,19.764 46.966,19.764 45.2,21.53 45.2,26.5 44.285,27.415 41.843,27.415 41.5,27.758 41.5,28 40.65,28.85 40.65,29.6 39.25,31 36.5,31 35.79,31.71 35.79,36.273 ; 35.79,36.273 37.673,36.273 38.2,36.8 38.2,37.725 37.7,38.225 37.7,40.2 43.65,40.2 46.66,37.19 46.66,28.96 45.8,28.1 45.4,28.1 44.7,28.8 44.7,30.3 44.2,30.8 43.8,30.8 43.3,30.3 43.3,29.125 42.275,28.1 ; 39.3,57.917 41.43,57.917 41.7,58.187 41.7,59.25 41.7,59.5 40.4,59.5 40.4,60.8 39.6,60.8 ; 39.3,57.917 39.3,60.5 39.6,60.8 ; 39.6,60.8 39.6,62.287 40.738,63.425 42.225,63.425 43.2,64.4 59.4,64.4 63.6,60.2 63.6,36.6 62.2,36.6 61.7,36.1 61.7,34.3 64.6,31.4 65,31.4 67.25,29.15 68.4,29.15 69.15,28.4 79.692,28.4 79.9,28.192 ; 50.8,26.2 51.3,26.7 51.3,36.072 52.05,36.822 52.05,40.8 48.621,44.229 46.4,46.45 46.4,51.4 48,53 48,55.515 48.585,56.1 50.6,56.1 51.1,56.1 51.385,55.815 51.385,54.315 53.1,52.6 53.1,50.5 51.4,48.8 50.2,48.8 49.2,47.8 49.2,46.6 50.1,45.7 51.7,45.7 55.4,42 55.4,26.2 58.9,22.7 ; 50.8,26.2 50,25.4 50,23.55 50,22.6 48.5,21.1 47.5,21.1 47,21.6 47,26.092 48.9,27.992 48.9,38.37 43.7,43.57 43.7,50.4 45.5,52.2 45.5,52.969 29.733,52.969 26.473,56.229 20.929,56.229 19.7,55 18.8,55 17.8,56 17.8,57.8 17.8,58.4 18.933,59.533 20.467,59.533 22,58 26.5,58 29.9,54.6 45.1,54.6 45.5,55 45.5,58.2 45.2,58.5 45.2,59.3 46.5,60.6 57.7,60.6 59.3,59 59.3,56.45 62,53.75 62,52.735 61.765,52.5 61.189,52.5 60.927,52.763 60.603,52.763 60.24,52.4 60.24,50.348 58.992,49.1 57.1,49.1 55.8,47.8 55.8,46.2 57.6,44.4 57.6,27.8 58.2,27.2 63.4,27.2 64.3,28.1 65.7,28.1 66.3,27.5 66.3,26.7 63.7,24.1 60.3,24.1 58.9,22.7 ; 65.4,63.6 65.4,60.2 65.9,59.7 ; 65.4,63.6 66.9,65.1 69.8,65.1 72.3,62.6 72.3,60.22 71.78,59.7 65.9,59.7 ; 79.9,28.192 78.7,26.992 78.7,24.125 74.2,19.625 74.2,16.3 74.2,15.8 74.6,15.4 75.9,15.4 76.61,16.11 76.61,19.277 80.7,23.367 80.7,27.408 ; 79.9,28.192 79.9,28.208 80.7,27.408 ; 79.92,55.42 80.8,55.42 ; 88.18,62.9 93.5,57.58 93.5,49 94.6,47.9 ; 88.18,62.9 81.4,62.9 81.1,62.6 81.1,57.745 85.229,57.745 87.755,57.745 89.7,55.8 89.7,48.3 91.59,46.41 91.59,18.91 94.3,16.2 95.7,16.2 96.1,16.6 96.1,18 ; 94.6,47.9 94.6,18.8 95.4,18 96.1,18
  lines w0.254: 8.55,57.842 8.55,49.95 6.7,48.1 6.7,42.1 7.65,41.15 7.65,32.2 9.8,30.05 9.8,26.1 11.7,24.2 11.7,20.2 13.6,18.3 13.7,18.3 14.6,18.3 15.2,18.9 15.2,20 12.9,22.3 12.9,24.6 11.4,26.1 11.4,40 11.9,40.5 11.9,48.9 14.8,51.8 14.8,57.9 14,58.7 12.25,58.7
  lines w0.5: 50.6,56.1 50.6,58.1 50.8,58.3 51.7,58.3 54.1,55.9 54.1,52.9 53.7,52.5 53.1,52.5 51.385,54.215 51.385,55.815 51.1,56.1 50.6,56.1
  text "NEGATIVE IMAGE" at 41,-15 h2.54
  text ".Layer_Name" at 41.25,-18.875 h2.54
GND_6 (plane layer: these items are gaps in the copper):
  lines w0.6: 6.875,0 6.875,10.125 6.875,11.875 8.1,13.1 9.75,13.1 11,11.85 11,10.5 9.025,8.525 9.025,7.587 9.025,3.275 10.1,2.2 24.575,2.2 24.575,5.225 24.575,8.425 22.85,10.15 22.85,12.1 22.85,13.15 19.75,16.25 19.75,17.75 20.25,18.25 22.75,18.25 28,13 29.525,11.475 29.525,10.55 30.75,9.325 31.1,8.975 31.1,7.131 30.25,6.281 28.781,6.281 27.5,5 27.5,2.75 27.95,2.3 40.8,2.3 42.5,4 42.5,5.2 41.6,6.1 39.9,6.1 38.8,7.2 38.8,10.05 38.8,13.05 39.25,13.5 39.25,14.7 38.1,15.85 38.1,17.6 38.8,18.3 40.1,18.3 42.15,16.25 46.5,16.25 47.5,15.25 47.5,11.6 47.5,2.5 56.5,2.5 56.5,14.75 57.75,16 59.5,16 60.8,14.7 60.8,11.05 60.8,2.2 66.125,2.2 66.125,3.125 69.525,3.125 69.525,2.1 78.95,2.1 78.95,3.2 78.975,3.225 83.25,3.225 83.25,0
  text "NEGATIVE IMAGE" at 41,-15 h2.54
  text ".Layer_Name" at 41.25,-18.875 h2.54
GND_9 (plane layer: these items are gaps in the copper):
  text "NEGATIVE IMAGE" at 41,-15 h2.54
  text ".Layer_Name" at 41.25,-18.875 h2.54

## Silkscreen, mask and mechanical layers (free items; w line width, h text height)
Top Overlay:
  drawing of 56 lines, arcs and shapes, not listed
  text "NFC" at 39,68.9 h2 r90
  text "SPI" at 62.6,68.5 h2 r90
  text "I2C" at 82.75,67.25 h2
  text "CAN" at 87.75,67.25 h2
  text "PWR" at 7.2,65.3 h2 r90
  text "RGB PARALLEL" at 19.25,64.75 h2
  text "CSI" at 52.2,63.95 h2
  text "ConnectCore® / for i.MX6UL SBC" at 80.645,62.865 h2
  text "LED1" at 14,61.2 h2
  text "CONSOLE" at 9.53,59 h2 r90
  text "SWD" at 15.6,56.192 h2
  text "RF CONTROL" at 96.25,52.75 h2 r90
  text "XBEE / MODULE" at 22,48.15 h1.8
  text "UART" at 4.75,47.5 h2 r90
  text "ConnectCore for / i.MX6UL Module" at 90.65,43.75 h1.5
  text "BOOT" at 4.5,37.75 h1.8 r90
  text "ANT EXT" at 93,34.75 h2
  text "IO EXT" at 10.1,34.6 h2
  text "XBEE" at 9.6,32.8 h1.8 r90
  text "GPIO" at 5.766,27.358 h2 r90
  text "RESET" at 20.8,25.7 h2
  text "ON/OFF" at 13.9,25.6 h2
  text "BT UART" at 96.5,19.25 h2 r90
  text "USB" at 5.25,18.25 h2 r90
  text "5V" at 96.5,16.5 h2 r90
  text "SPK" at 59.575,15.575 h2
  text "USB" at 49.75,15.25 h2
  text "PWR" at 84.75,13 h2
  text "HEADPHONE" at 69,12.5 h2
  text "3.3V" at 96.5,12.25 h2 r90
  text "5VDC" at 91.5,12.1 h2
  text "WLAN" at 3.75,5.75 h2
  text "ETH2" at 8,1.25 h2 r90
  text "ETH1" at 26.5,1.25 h2 r90
  text "AUDIO" at 62,0.75 h2 r90
  text ".Layer_Name" at 41.5,-18.75 h2.54
Bottom Overlay:
  drawing of 1409 lines, arcs and shapes, not listed
  text "LVDS" at 10.5,63 h2
  text "SWD" at 13.792,54.009 h2 r270
  text "MICRO SIM" at 97,45.75 h2
  text "JTAG" at 13.5,36.25 h2 r270
  text "IO EXT" at 16.5,23.75 h2
  text "PCI EXPRESS / MINI CARD" at 47.1,22.6 h2
  text "MICRO SD" at 82,9.25 h1.8 r270
  text "USB OTG" at 55.2,8.5 h2
  text "COIN CELL" at 95.25,5.5 h2
  text ".Layer_Name" at 69.25,-19.25 h2.54
Top Paste:
  text ".Layer_Name" at 39.548,-18.889 h2.54
Bottom Paste:
  text ".Layer_Name" at 37.409,-19.018 h2.54
Top Solder:
  text ".Layer_Name" at 38.026,-18.881 h2.54
Bottom Solder:
  text ".Layer_Name" at 37.014,-19.018 h2.54
Board Outline:
  lines w0.1: 68.471,50.54 83.093,50.54 cw(c83.093,50.053) 83.58,50.053 83.58,32.863 cw(c83.057,32.863) 83.057,32.34 68.5,32.34 cw(c68.5,32.92) 67.92,32.92 67.92,49.96 cw(c68.5,49.96) 68.5,50.54
  lines w0.25: 0,0 100.05,0 100.05,72 0,72 0,0
Top Assembly:
  drawing of 58 lines, arcs and shapes, not listed
  text "2" at 27.432,122.428 h4.57
  text "1" at 179.832,122.428 h4.57
  text "B" at -25.908,75.438 h7.11
  text "B" at 230.632,75.438 h7.11
  text "1. Assemble in accordance with IPC-A-610, class 2." at 110,68 h5
  text ".Layer_Name" at 37.75,-19 h2.54
  text "CAD GENERATED:" at 169.164,-30.48 h1.27
  text ".pcb_File_Name_No_Path" at 184.658,-30.48 h2.17
  text "A" at -25.908,-31.242 h7.11
  text "A" at 230.632,-31.242 h7.11
  text "EXCEPT AS MAY BE OTHERWISE PROVIDED BY" at 70.104,-34.544 h2.17
  text "WIRELESS DESIGN SERVICES" at 164.084,-36.068 h2.54
  text "CONTRACT, THIS DOCUMENT IS THE PROPERTY" at 70.104,-36.576 h2.17
  text "OF DIGI INTERNATIONAL.  IF RELEASED TO OTHER" at 70.104,-38.608 h2.17
  text "11001 Bren Road East" at 164.084,-39.624 h2.54
  text "SOURCES, IT SHALL BE RECEIVED BY SUCH" at 70.104,-40.64 h2.17
  text "SOURCES IN TOTAL CONFIDENCE AND SHALL NOT" at 70.104,-42.672 h2.17
  text "Minnetonka, MN 55343" at 164.592,-43.18 h2.54
  text "BE RELEASED TO ANY THIRD PARTY OR PARTIES," at 70.104,-44.704 h2.17
  text "NOR USED FOR MANUFACTURE OR SALE OF THE" at 70.104,-46.736 h2.17
  text "ARTICLES WITHOUT PRIOR WRITTEN" at 70.104,-48.768 h2.17
  text "DIGI INTERNATIONAL" at 160.02,-49.276 h2.54
  text "AUTHORIZATION." at 70.104,-50.8 h2.17
  text "ConnectCore for i.MX6UL" at 155.448,-53.34 h2.54
  text "ENGINEER" at 69.596,-57.404 h1.27
  text "SINGLE BOARD COMPUTER (SBC)" at 147.32,-57.404 h2.54
  text "Sebastien Meyer" at 86.36,-58.42 h1.27
  text "PCB DESIGNER" at 69.596,-62.484 h1.27
  text "SIZE" at 122.936,-62.484 h1.27
  text "CAGE NO." at 131.064,-62.484 h1.27
  text "ASSM NO." at 159.004,-62.484 h1.27
  text "REV." at 220.98,-62.484 h1.27
  text "Josh Flagstad" at 86.36,-63.5 h1.27
  text ".VariantName" at 180.34,-66.294 h2.54
  text "DATE" at 69.596,-67.056 h1.27
  text "A" at 123.444,-67.056 h2.54
  text ".VariantRevision" at 220.98,-67.056 h2.54
  text ".Print_Date" at 86.36,-68.072 h1.27
  text "JIRA EPIC:" at 69.596,-72.136 h1.27
  text "CC6UL-244" at 86.36,-73.66 h1.27
  text ".Print_Scale" at 120.904,-73.66 h1.27
  text "SVN HEAD REV:" at 146.304,-73.66 h1.27
  text ".VersionControl_RevNumber" at 162.052,-73.66 h1.27
  text "SHEET:" at 184.404,-73.66 h1.27
  text "1 OF 1" at 202.946,-73.66 h1.27
  text "2" at 27.432,-80.772 h4.57
  text "1" at 179.832,-80.772 h4.57
Bottom Assembly:
  drawing of 59 lines, arcs and shapes, not listed
  text "1" at 27.432,122.428 h4.57
  text "2" at 179.832,122.428 h4.57
  text "B" at -23.368,75.438 h7.11
  text "B" at 233.172,75.438 h7.11
  text "1. Assemble in accordance with IPC-A-610, class 2." at 212,68 h5
  text ".Layer_Name" at 70.324,-19.016 h2.54
  text ".pcb_File_Name_No_Path" at 22.606,-30.48 h2.17
  text "CAD GENERATED:" at 38.1,-30.48 h1.27
  text "A" at -23.368,-31.242 h7.11
  text "A" at 233.172,-31.242 h7.11
  text "EXCEPT AS MAY BE OTHERWISE PROVIDED BY" at 137.16,-34.544 h2.17
  text "WIRELESS DESIGN SERVICES" at 43.18,-36.068 h2.54
  text "CONTRACT, THIS DOCUMENT IS THE PROPERTY" at 137.16,-36.576 h2.17
  text "OF DIGI INTERNATIONAL.  IF RELEASED TO OTHER" at 137.16,-38.608 h2.17
  text "11001 Bren Road East" at 43.18,-39.624 h2.54
  text "SOURCES, IT SHALL BE RECEIVED BY SUCH" at 137.16,-40.64 h2.17
  text "SOURCES IN TOTAL CONFIDENCE AND SHALL NOT" at 137.16,-42.672 h2.17
  text "Minnetonka, MN 55343" at 42.672,-43.18 h2.54
  text "BE RELEASED TO ANY THIRD PARTY OR PARTIES," at 137.16,-44.704 h2.17
  text "NOR USED FOR MANUFACTURE OR SALE OF THE" at 137.16,-46.736 h2.17
  text "ARTICLES WITHOUT PRIOR WRITTEN" at 137.16,-48.768 h2.17
  text "DIGI INTERNATIONAL" at 47.244,-49.276 h2.54
  text "AUTHORIZATION." at 137.16,-50.8 h2.17
  text "ConnectCore for i.MX6UL" at 51.816,-53.34 h2.54
  text "SINGLE BOARD COMPUTER (SBC)" at 59.944,-57.404 h2.54
  text "ENGINEER" at 137.668,-57.404 h1.27
  text "Sebastien Meyer" at 120.904,-58.42 h1.27
  text "REV." at -13.716,-62.484 h1.27
  text "ASSM NO." at 48.26,-62.484 h1.27
  text "CAGE NO." at 76.2,-62.484 h1.27
  text "SIZE" at 84.328,-62.484 h1.27
  text "PCB DESIGNER" at 137.668,-62.484 h1.27
  text "Josh Flagstad" at 120.904,-63.5 h1.27
  text ".VariantName" at 26.924,-66.294 h2.54
  text ".VariantRevision" at -13.716,-67.056 h2.54
  text "A" at 83.82,-67.056 h2.54
  text "DATE" at 137.668,-67.056 h1.27
  text ".Print_Date" at 120.904,-68.072 h1.27
  text "JIRA EPIC:" at 137.668,-72.136 h1.27
  text "1 OF 1" at 4.318,-73.66 h1.27
  text "SHEET:" at 22.86,-73.66 h1.27
  text ".VersionControl_RevNumber" at 45.212,-73.66 h1.27
  text "SVN HEAD REV:" at 60.96,-73.66 h1.27
  text ".Print_Scale" at 86.36,-73.66 h1.27
  text "CC6UL-244" at 120.904,-73.66 h1.27
  text "1" at 27.432,-80.772 h4.57
  text "2" at 179.832,-80.772 h4.57
Cavity Solder Mask:
  the board outline again, w0.25
Panel:
  lines w0.1: 68.471,50.54 83.093,50.54 cw(c83.093,50.053) 83.58,50.053 83.58,32.863 cw(c83.057,32.863) 83.057,32.34 68.5,32.34 cw(c68.5,32.92) 67.92,32.92 67.92,49.96 cw(c68.5,49.96) 68.5,50.54 ; 170.971,50.54 185.593,50.54 cw(c185.593,50.053) 186.08,50.053 186.08,32.863 cw(c185.557,32.863) 185.557,32.34 171,32.34 cw(c171,32.92) 170.42,32.92 170.42,49.96 cw(c171,49.96) 171,50.54 ; 273.471,50.54 288.093,50.54 cw(c288.093,50.053) 288.58,50.053 288.58,32.863 cw(c288.057,32.863) 288.057,32.34 273.5,32.34 cw(c273.5,32.92) 272.92,32.92 272.92,49.96 cw(c273.5,49.96) 273.5,50.54
  lines w0.25: 192.5,74.5 215,74.5 cw(c215,73.25) 215,72 205,72 205,62 cw(c203.75,62) 202.5,62 202.5,72 192.54,72 cw(c192.54,73.25) 192.54,74.5 ; 287.5,72 222.5,72 cw(c222.5,73.25) 222.5,74.5 287.5,74.5 ; 287.58,72 ccw(c287.58,73.25) 287.58,74.5 ; 295,72 305,72 305,62 ccw(c306.25,62) 307.5,62 307.5,72 ccw(c305,72) 305,74.5 295,74.5 ; 295.08,72 cw(c295.08,73.25) 295.08,74.5 ; 60.975,0 cw(c60.975,-1.25) 62.225,-1.25 ; 60.975,0 cw(c60.975,-1.25) 62.225,-1.25 ; 60.975,0 0,0 0,10 ccw(c-1.25,10) -2.5,10 -2.5,-2.75 ccw(c-1.25,-2.75) -1.25,-4 60.975,-4 ccw(c60.975,-2.75) 62.225,-2.75 62.225,-1.25 ; 66.225,-1.25 cw(c67.475,-1.25) 67.475,0 ; 66.225,-1.25 cw(c67.475,-1.25) 67.475,0 ; 66.225,-1.25 66.225,-2.75 ccw(c67.475,-2.75) 67.475,-4 93,-4 163.475,-4 ccw(c163.475,-2.75) 164.725,-2.75 164.725,-1.25 ccw(c163.475,-1.25) 163.475,0 102.5,0 102.5,10 ccw(c101.25,10) 100,10 100,0 67.475,0 ; -15,-11.5 -15,79.5 320,79.5 320,-11.5 -15,-11.5 ; -2.5,17.5 ccw(c-1.25,17.5) 0,17.5 0,54.5 ccw(c-1.25,54.5) -2.5,54.5 -2.5,17.5 ; -2.5,62 ccw(c-1.25,62) 0,62 0,72 10,72 ccw(c10,73.25) 10,74.5 0,74.5 ccw(c0,72) -2.5,72 -2.5,62 ; 17.5,72 cw(c17.5,73.25) 17.5,74.5 82.5,74.5 cw(c82.5,73.25) 82.5,72 17.5,72 ; 90,72 cw(c90,73.25) 90,74.5 112.54,74.5 cw(c112.54,73.25) 112.54,72 102.5,72 102.5,62 cw(c101.25,62) 100,62 100,72 90,72 ; 100,16.25 ccw(c101.25,16.25) 102.5,16.25 102.5,54.5 ccw(c101.25,54.5) 100,54.5 100,16.25 ; 120,72 cw(c120,73.25) 120,74.5 185,74.5 cw(c185,73.25) 185,72 120,72 ; 168.725,-2.75 ccw(c169.975,-2.75) 169.975,-4 266.05,-4 ccw(c266.05,-2.75) 267.3,-2.75 267.3,-1.25 ccw(c266.05,-1.25) 266.05,0 205,0 205,10 ccw(c203.75,10) 202.5,10 202.5,0 169.975,0 ccw(c169.975,-1.25) 168.725,-1.25 168.725,-2.75 ; 202.5,16.25 ccw(c203.75,16.25) 205,16.25 205,54.5 ccw(c203.75,54.5) 202.5,54.5 202.5,16.25 ; 271.3,-2.75 ccw(c272.55,-2.75) 272.55,-4 306.25,-4 ccw(c306.25,-2.75) 307.5,-2.75 307.5,10 ccw(c306.25,10) 305,10 305,0 272.55,0 ccw(c272.55,-1.25) 271.3,-1.25 271.3,-2.75 ; 305,16.25 ccw(c306.25,16.25) 307.5,16.25 307.5,54.5 ccw(c306.25,54.5) 305,54.5 305,16.25
  text ".Layer_Name" at 41.25,-18.875 h2.54
PCB Name:
  text "CC6UL SBC" at 36.25,-24.125 h2.54
Fab/Dimension:
  circle w0.05: c3,3 r3.111
  circle w0.05: c3,69 r3.111
  circle w0.05: c97,69 r3.111
  circle w0.05: c97,3 r3.111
